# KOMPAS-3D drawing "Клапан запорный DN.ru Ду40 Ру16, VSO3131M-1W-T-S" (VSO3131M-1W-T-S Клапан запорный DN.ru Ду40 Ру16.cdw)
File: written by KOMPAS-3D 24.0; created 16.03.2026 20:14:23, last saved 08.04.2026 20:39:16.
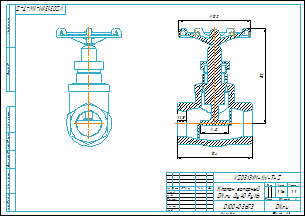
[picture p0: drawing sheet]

Document properties: c3d_UniqueCompID: 94d3474e-3e6e-4ddd-ad0b-ef51eb5e31da; Обозначение: VSO3131M-1W-T-S; Наименование: Клапан запорный DN.ru Ду32 Ру16; Материал: Сталь 10 ГОСТ 1050-2013; Автор: artiomk228874@gmail.com; Класс точности: c; Знак неуказанной шероховатости: Шероховатость не задана; Рассекать на разрезах: Да; Автор: artiomk228874@gmail.com; Форматы листов документа: A3; Полное имя файла: VSO3131M-1W-T-S Клапан запорный DN.ru Ду40 Ру16.m3d; Масса: 1.16; Наименование: Клапан запорный DN.ru Ду40 Ру16; Количество листов документа: 1; Примечание: D100-03673

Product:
- Body: Тело 1  | qty 1
    Масса: 1.890349
- Part/product: Клапан запорный DN.ru Ду40 Ру16  | designation VSO3131M-1W-T-S
    Масса: 1.16
    Раздел спецификации: Прочие изделия
    Форматы листов документа: A3
    Примечание: D100-03673
    additional columns: 94d3474e-3e6e-4ddd-ad0b-ef51eb5e31da; VSO3131M-1W-T-S; Клапан запорный DN.ru Ду32 Ру16; Сталь 10 ГОСТ 1050-2013; artiomk228874@gmail.com; c; Шероховатость не задана; Да

Views: Проекционный вид 2
Referenced files in C:\Users\artio\OneDrive\Рабочий стол\Клапан запорный DN.ru VSO3131M-1W-T-S Ду15-Ду50 Ру16\Ду40\: VSO3131M-1W-T-S Клапан запорный DN.ru Ду40 Ру16.m3d, VSO3131M-1W-T-S Клапан запорный DN.ru Ду40 Ру16.cdw
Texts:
  VSO3131M-1W-T-S
  Клапан запорный
  DN.ru Ду40 Ру16
  Клапан запорный DN.ru Ду40 Ру16
  VSO3131M-1W-T-S Клапан запорный DN.ru Ду40 Ру16
Dimensions and other numbers on the sheet: 0; 3; 4; 1:1; 1; 2; 1,16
